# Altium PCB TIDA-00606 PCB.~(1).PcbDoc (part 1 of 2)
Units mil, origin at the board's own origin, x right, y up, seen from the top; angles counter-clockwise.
Board outline 3100 x 2950 mil, 4 copper layers (Top Layer, InternalPlane1, MidLayer1, Bottom Layer); 112 components, 59 nets, 260 pads, 440 vias.
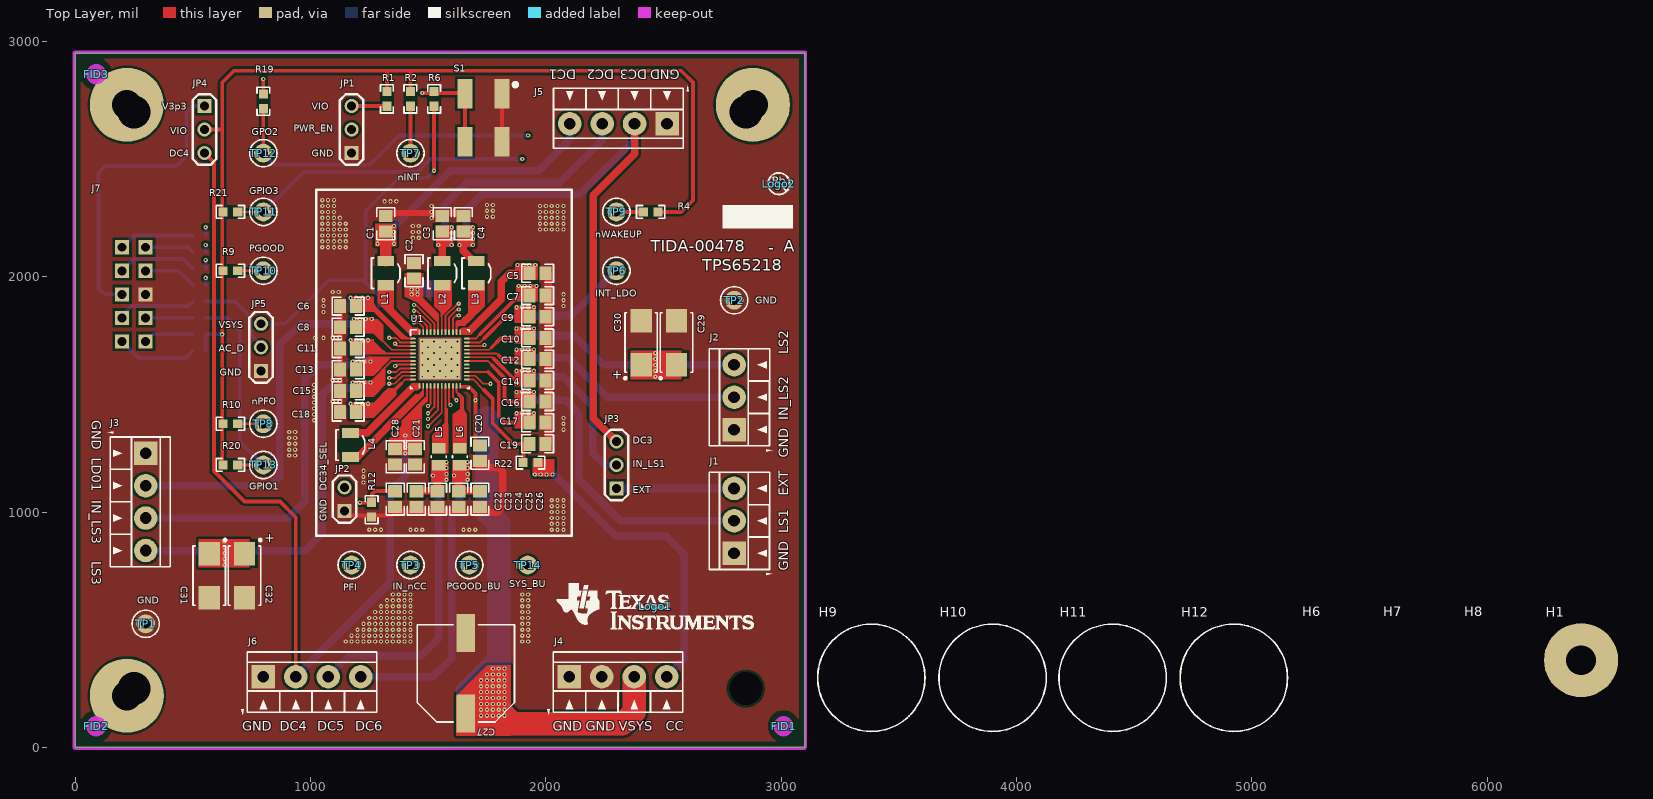
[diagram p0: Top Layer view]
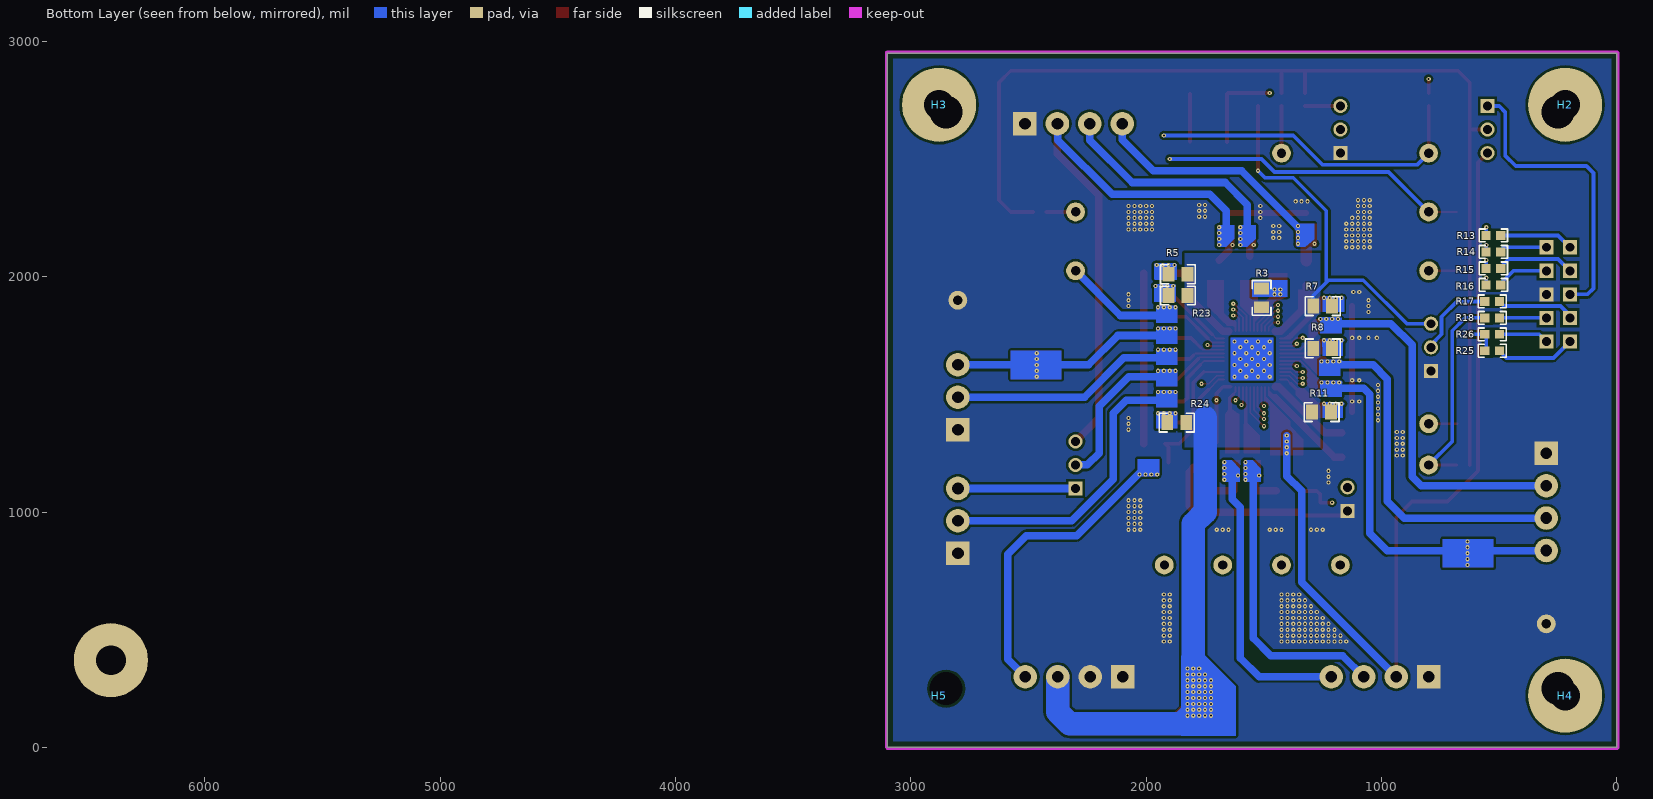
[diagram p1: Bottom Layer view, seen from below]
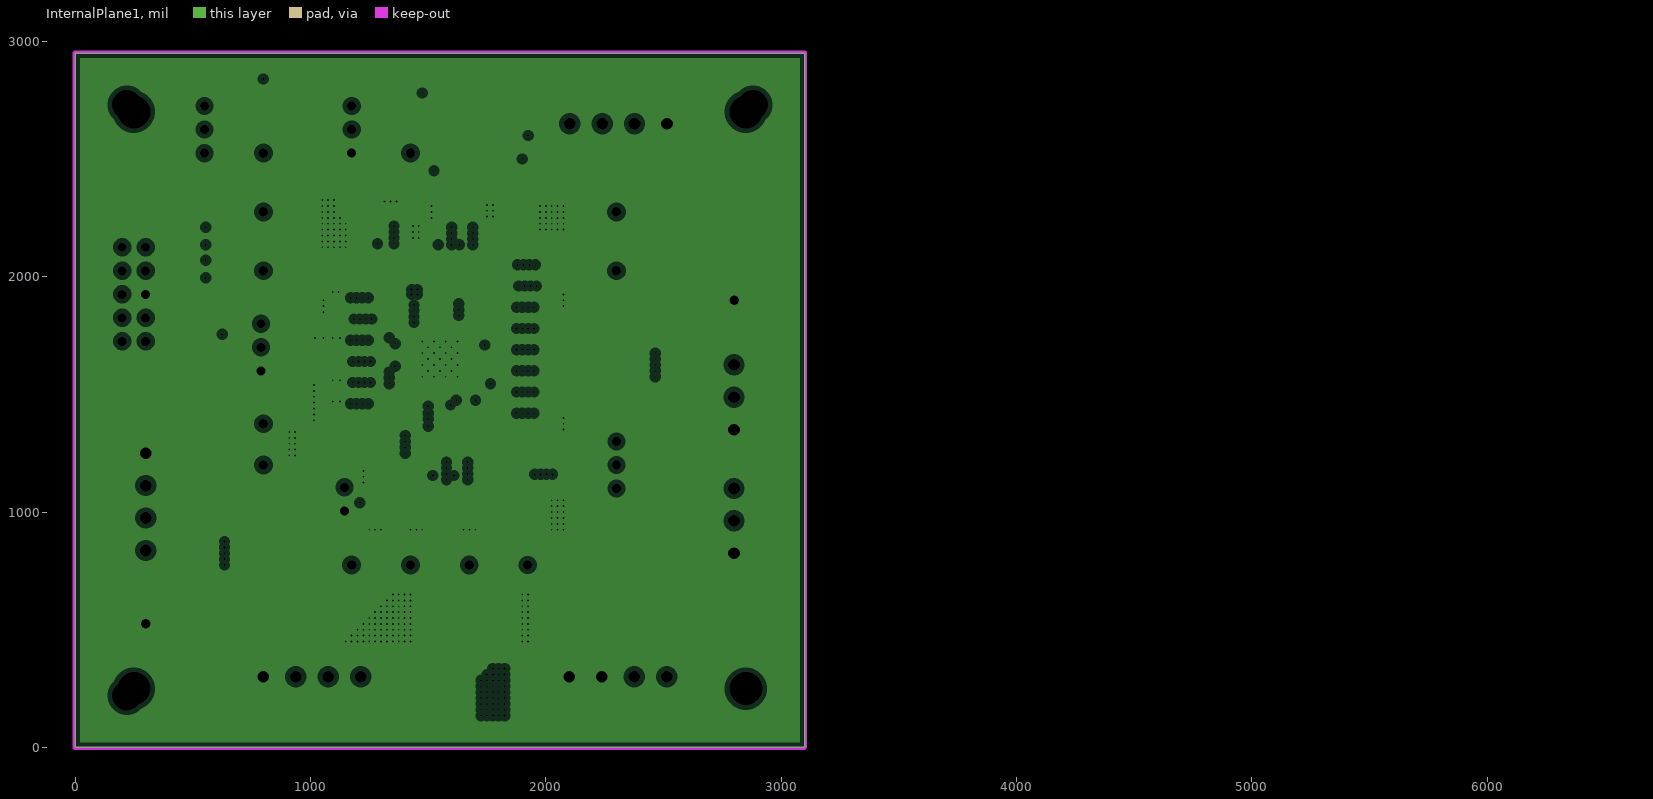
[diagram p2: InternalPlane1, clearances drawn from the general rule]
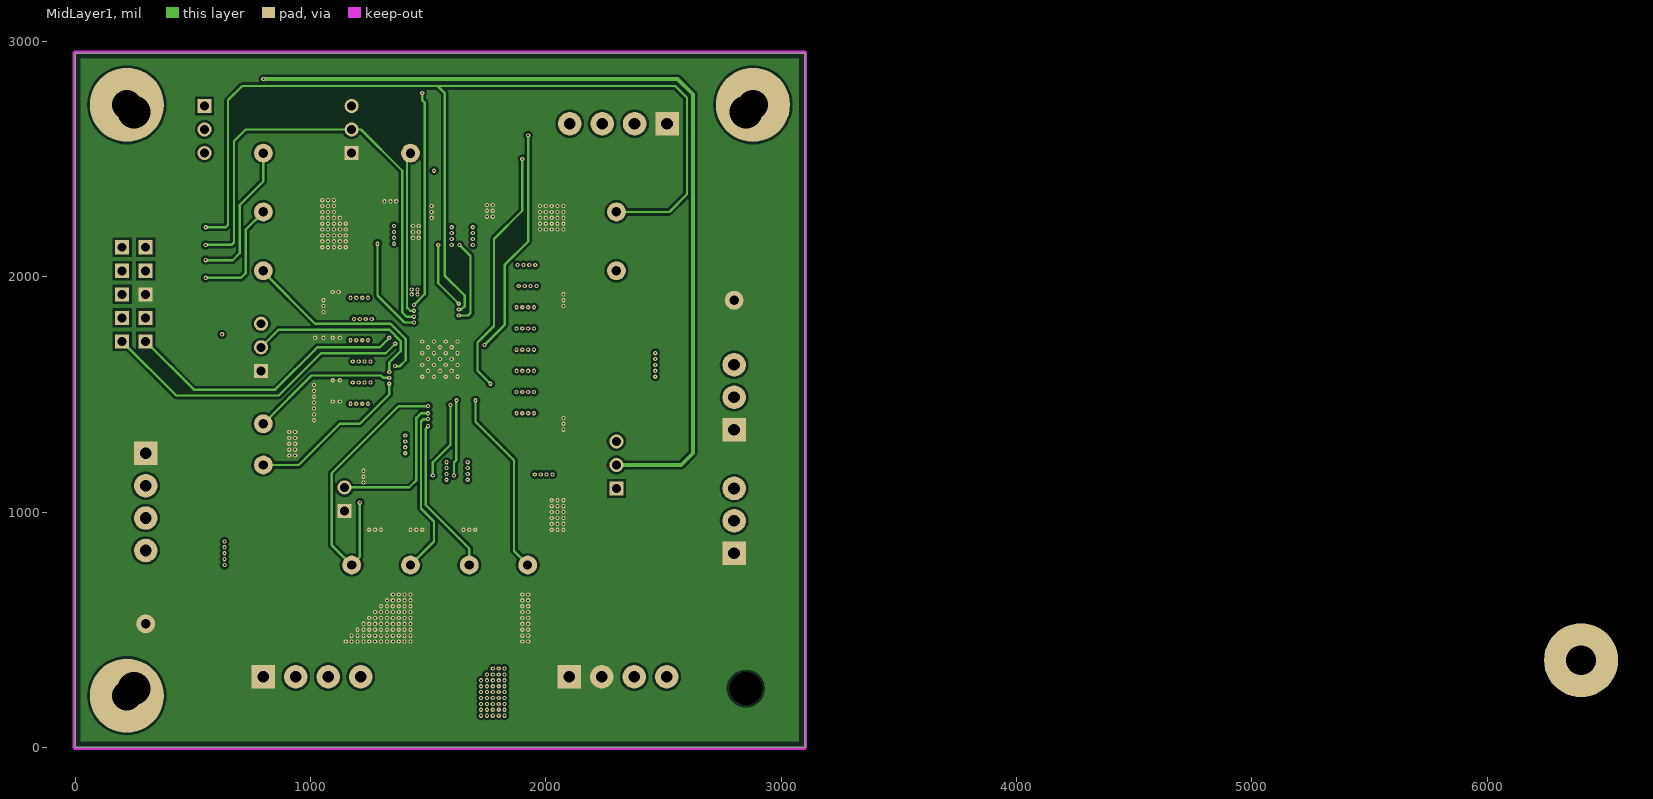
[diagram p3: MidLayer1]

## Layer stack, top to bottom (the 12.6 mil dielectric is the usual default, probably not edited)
Top Solder: solder mask 0.4, Solder Resist, Dk 3.5
Top Layer: signal copper 2.8
Dielectric1: core 12.6, FR-4, Dk 4.8
InternalPlane1: plane copper 2.1, net GND
Dielectric3: prepreg 12.6, FR-4, Dk 4.8
MidLayer1: signal copper 2.1
Dielectric2: core 12.6, FR-4, Dk 4.8
Bottom Layer: signal copper 2.8
Bottom Solder: solder mask 0.4, Solder Resist, Dk 3.5

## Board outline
0,0 3100,0 3100,2950 0,2950

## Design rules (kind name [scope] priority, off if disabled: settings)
AcuteAngle [All] p1: minimum=4.50000000000000E+0001 checktracksonly=FALSE
AssemblyTestPointUsage [All] p1 off: valid=2
AssemblyTestpoint [All] p1 off: testpointundercomponent=TRUE minsize=40 maxsize=100 preferedsize=60 minholesize=0 maxholesize=40 preferedholesize=32 testpointgrid=1 usegrid=TRUE gridtolerance=0.01 allowsidetop=TRUE allowsidebottom=TRUE
Clearance Clearance_BoardEdge_MountingHoles [OnCopper and InComponentClass('Mounting Holes') vs IsKeepOut] p1: gap=40
Clearance Clearance_BoardEdge_Poly [OnCopper and InPoly vs IsKeepOut] p2: gap=25
Clearance Clearance_BoardEdge [OnCopper and Not InComponentClass('Logo') and not InComponentClass('FiducialMark') and not InRegion(1000,500,4000,800) and Not IsKeepout vs IsKeepOut] p3: gap=50
Clearance Clearance_Poly [InPolygon] p4: gap=10
Clearance [All] p5: gap=5
ComponentClearance ComponentClearance_Shunt [InComponentClass('Header') vs InComponentClass('Shunt')] p1: gap=0 collisioncheckmode=3 verticalgap=0 showdistances=FALSE
ComponentClearance ComponentClearance_MountingHoles_FiducialMarks [InComponentClass('Mounting Holes') vs InComponentClass('FiducialMark')] p2: gap=50 collisioncheckmode=3 verticalgap=10 showdistances=FALSE
ComponentClearance ComponentClearance_Logo [InComponentClass('Logo')] p3: gap=50 collisioncheckmode=3 verticalgap=10 showdistances=FALSE
ComponentClearance ComponentClearance_ScrewToNut [(HasFootprint('NY PMS 440 0025 PH')) vs (HasFootprint('Keystone_1902C'))] p4: gap=5 collisioncheckmode=3 verticalgap=10 showdistances=FALSE
ComponentClearance ComponentClearance_MountingHoles [InComponentClass('Mounting Holes')] p5: gap=250 collisioncheckmode=3 verticalgap=100000 showdistances=FALSE
ComponentClearance ComponentClearance_SmallPassives [HasFootprint('0201*') or HasFootprint('0402*') or HasFootprint('0508') or HasFootprint('0603*') or HasFootprint('0612') or HasFootprint('0805*') or HasFootprint('0815*') or HasFootprint('0830*') or HasFootprint('1206*') or HasFootprint('1210*') or HasFootprint('1808*') or HasFootprint('1812*') or HasFootprint('1825*') or HasFootprint('2010*') or HasFootprint('2220*') or HasFootprint('2225*') or HasFootprint('2512*') or HasFootprint('2728*') or HasFootprint('3518*') vs HasFootprint('0201*') or HasFootprint('0402*') or HasFootprint('0508') or HasFootprint('0603*') or HasFootprint('0612') or HasFootprint('0805*') or HasFootprint('0815*') or HasFootprint('0830*') or HasFootprint('1206*') or HasFootprint('1210*') or HasFootprint('1808*') or HasFootprint('1812*') or HasFootprint('1825*') or HasFootprint('2010*') or HasFootprint('2220*') or HasFootprint('2225*') or HasFootprint('2512*') or HasFootprint('2728*') or HasFootprint('3518*')] p6: gap=20 collisioncheckmode=3 verticalgap=10 showdistances=FALSE
ComponentClearance ComponentClearance_THtoSMT [IsThruComponent vs IsSMTComponent] p7: gap=10 collisioncheckmode=3 verticalgap=30 showdistances=FALSE
ComponentClearance ComponentClearance_THtoTH [IsThruComponent vs IsThruComponent] p8: gap=10 collisioncheckmode=3 verticalgap=30 showdistances=FALSE
ComponentClearance [All] p9: gap=10 collisioncheckmode=3 verticalgap=10 showdistances=FALSE
DiffPairsRouting [All] p1: maxlimit=100 minlimit=10 mostfreqgap=10 toplayer_minwidth=15 toplayer_maxwidth=15 toplayer_prefwidth=15 midlayer2_minwidth=15 midlayer2_maxwidth=15 midlayer2_prefwidth=15 bottomlayer_minwidth=15 bottomlayer_maxwidth=15 bottomlayer_prefwidth=15 maxuncoupledlength=1000
FabricationTestPointUsage TestPointUsage [All] p1: valid=2 allowmultiple=FALSE
FabricationTestpoint Testpoint [All] p1: side=3 testpointundercomponent=TRUE minsize=40 maxsize=100 preferedsize=60 minholesize=0 maxholesize=40 preferedholesize=32 testpointgrid=1 allowsidetop=TRUE allowsidebottom=TRUE usegrid=TRUE gridtolerance=0.01
FanoutControl Fanout_LCC [IsLCC] p1: bgadir=Out bgaviamode=Centered fanoutstyle=Auto fanoutdirection=Alternating viagrid=1 // Fanout_LCC (Default Rule)
FanoutControl Fanout_BGA [IsBGA] p2: bgadir=Out bgaviamode=Centered fanoutstyle=Auto fanoutdirection=Alternating viagrid=1 // Fanout_BGA (Default Rule)
FanoutControl Fanout_Default [All] p4: bgadir=Out bgaviamode=Centered fanoutstyle=Auto fanoutdirection=Alternating viagrid=1 // Fanout_Default (Default Rule)
FanoutControl Fanout_Small [(CompPinCount < 5)] p5: bgadir=Out bgaviamode=Centered fanoutstyle=Auto fanoutdirection=OutThenIn viagrid=1 // Fanout_Small (Default Rule)
HoleSize [All] p1: absolutevalues=TRUE maxlimit=251 minlimit=8 maxpercent=80.000 minpercent=20.000
MinimumAnnularRing MinimumAnnularRing_ThermalPadVias [IsVia and InAnyComponent] p1: minimumring=5
MinimumAnnularRing [All] p2: minimumring=5
MinimumSolderMaskSliver MinimumSolderMaskSliver_Logo [InComponentClass('Logo') vs InComponentClass('Logo')] p1: minsoldermaskwidth=0.7
MinimumSolderMaskSliver [All] p2: minsoldermaskwidth=4
PlaneClearance [All] p1: clearance=20
PlaneConnect [All] p1: planeconnectstyle=Direct reliefexpansion=10 reliefentries=4 reliefconductorwidth=10 reliefairgap=10
PolygonConnect [All] p1: connectstyle=Direct reliefconductorwidth=10 reliefentries=4 polygonreliefangle="90 Angle" airgapwidth=10
RoutingVias ThermalPadVias [IsVia and InAnyComponent] p1: holewidth=7.87 width=19.68 viastyle="Through Hole" minholewidth=7.87 minwidth=18 maxholewidth=12.99 maxwidth=23.62
RoutingVias [All] p2: holewidth=16 width=34 viastyle="Through Hole" minholewidth=7.87 minwidth=18 maxholewidth=40 maxwidth=65
SMDToCorner [All] p1: distance=25000
SilkToSilkClearance SilkToSilkClearance_Pb-FreeLogo [(HasFootprint('Pb-Free_Overlay_Medium') OR HasFootprint('Pb-Free_Overlay_Small')) vs (HasFootprint('Pb-Free_Overlay_Medium') OR HasFootprint('Pb-Free_Overlay_Small'))] p1: silktosilkclearance=0
SilkToSilkClearance [All] p2: silktosilkclearance=5
SilkToSolderMaskClearance SilkscreenOverComponentPads [IsPad] p1: minsilkscreentomaskgap=4.5 clearancetoexposedcopper=TRUE
SolderMaskExpansion [All] p1: expansion=0
UnpouredPolygon [All] p1: allowunpoured=FALSE
Width [All] p1: maxlimit=100 minlimit=6 preferedwidth=10 checkconnectedcopper=TRUE
13 further rules are at their usual default settings.

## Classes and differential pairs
component class "Mounting Holes": H1 H2 H3 H4
component class TIDA0606: C1 C2 C3 C4 C5 C6 C7 C8 C9 C10 C11 C12 C13 C14 C15 C16 C17 C18 C19 C20 C21 C22 C23 C24 C25 C26 C27 C28 C29 C30 C31 C32 J1 J2 J3 J4 J5 J6 J7 JP1 JP2 JP3 JP4 JP5 L1 L2 L3 L4 L5 L6 R1 R2 R3 R4 R5 R6 R7 R8 R9 R10 R11 R12 R13 R14 R15 R16 R17 R18 R19 R20 R21 R22 R23 R24 R25 R26 S1 TP1 TP2 TP3 TP4 TP5 TP6 TP7 TP8 TP9 TP10 TP11 TP12 TP13 TP14 U1
component class Logo: Logo1
component class TID_Hardware: FID1 FID2 FID3 H1 H2 H3 H4 H5 H6 H7 H8 H9 H10 H11 H12 Logo1 Logo2 ZZ2 ZZ3 ZZ4
component class FiducialMark: FID1 FID2 FID3
component class AssemblyNote: ZZ3 ZZ4

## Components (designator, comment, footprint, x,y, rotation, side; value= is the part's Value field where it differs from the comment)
C1 "C2012X7R0J106K125AB" 0805 1320,2225 r90 top
C2 "C2012X7R1A475K125AC" 0805 1440,2025 r90 top
C3 "C2012X7R0J106K125AB" 0805 1560,2225 r90 top
C4 "C2012X7R0J106K125AB" 0805 1650,2225 r90 top
C5 "C2012X7R1A475K125AC" 0805 1965,2014.68 r0 top
C6 "C2012X7R1A475K125AC" 0805 1160,1875 r0 top
C7 "C2012X7R1A475K125AC" 0805 1965,1919.68 r0 top
C8 "C2012X7R0J106K125AB" 0805 1160,1785 r0 top
C9 "C0805C104K8RACTU" 0805 1965,1829.68 r0 top
C10 "C2012X7R1A106K125AC" 0805 1965,1739.68 r0 top
C11 "C2012X7R1A475K125AC" 0805 1160,1695 r0 top
C12 "C2012X7R1A475K125AC" 0805 1965,1649.68 r0 top
C13 "C2012X7R1C475K125AE" 0805 1160,1605 r0 top
C14 "C2012X7R1A475K125AC" 0805 1965,1559.68 r0 top
C15 "CL21B106KOQNNNE" 0805 1160,1515 r0 top
C16 "C2012X7R1A106K125AC" 0805 1965,1469.68 r0 top
C17 "C2012X7R1A475K125AC" 0805 1965,1379.68 r0 top
C18 "C2012X7R1A475K125AC" 0805 1160,1425 r0 top
C19 "C2012X7R1A475K125AC" 0805 1965,1289.68 r0 top
C20 "CL21B105KPFNNNE" 0805 1720,1250 r90 top
C21 "C0805C104K8RACTU" 0805 1445,1235 r90 top
C22 "C0805C104K8RACTU" 0805 1360,1055 r90 top
C23 "C2012X7R1A106K125AC" 0805 1450,1055 r90 top
C24 "C2012X7R1A106K125AC" 0805 1540,1055 r90 top
C25 "C2012X7R1A106K125AC" 0805 1630,1055 r90 top
C26 "C2012X7R1A106K125AC" 0805 1720,1055 r90 top
C27 "EEE-1EA471UAP" SM_RADIAL_G 1660,315 r90 top
C28 "C2012X5R1A476M125AC" 0805 1360,1235 r90 top
C29 "T495C686M016ZTE250" 6032-28 2555,1720 r90 top
C30 "T495C686M016ZTE250" 6032-28 2405,1720 r90 top
C31 "T495C686M016ZTE250" 6032-28 570,730 r270 top
C32 "T495C686M016ZTE250" 6032-28 720,730 r270 top
FID1 "Fiducial" Fiducial10-20 3010,90 r0 top
FID2 "Fiducial" Fiducial10-20 90,90 r0 top
FID3 "Fiducial" Fiducial10-20 90,2860 r0 top
H1 "NY PMS 440 0025 PH" "NY PMS 440 0025 PH" 6398,371 r0 top
H2 "NY PMS 440 0025 PH" "NY PMS 440 0025 PH" 220,2730 r180 bottom
H3 "NY PMS 440 0025 PH" "NY PMS 440 0025 PH" 2880,2730 r180 bottom
H4 "NY PMS 440 0025 PH" "NY PMS 440 0025 PH" 220,220 r180 bottom
H5 "1902C" Keystone_1902C#1 2880,220 r180 bottom
H6 "1902C" Keystone_1902C#2 5353,401 r0 top
H7 "1902C" Keystone_1902C#2 5698,401 r0 top
H8 "1902C" Keystone_1902C#2 6043,401 r0 top
H9 "SJ-5303 (CLEAR)" Bumpon_SJ5003Transparent 3383,296 r0 top
H10 "SJ-5303 (CLEAR)" Bumpon_SJ5003Transparent 3898,296 r0 top
H11 "SJ-5303 (CLEAR)" Bumpon_SJ5003Transparent 4408,296 r0 top
H12 "SJ-5303 (CLEAR)" Bumpon_SJ5003Transparent 4923,296 r0 top
J1 "ED555/3DS" TERM_BLK_ED555-3DS 2800,825 r90 top
J2 "ED555/3DS" TERM_BLK_ED555-3DS 2800,1350 r90 top
J3 "ED555/4DS" TERM_BLK_ED555-4DS 300,1250 r270 top
J4 "ED555/4DS" TERM_BLK_ED555-4DS 2100,300 r0 top
J5 "ED555/4DS" TERM_BLK_ED555-4DS 2515,2650 r180 top
J6 "ED555/4DS" TERM_BLK_ED555-4DS 800,300 r0 top
J7 "CONN_2510-6002UB" CONN_2510-6002UB 200,2125 r270 top
JP1 "PWR_EN" HDR100_1X3 1175,2525 r90 top
JP2 "DC34_SEL" HDR100_1X2 1145,1005 r90 top
JP3 "IN_LS1" HDR100_1X3 2300,1100 r90 top
JP4 "VIO" HDR100_1X3 550,2725 r270 top
JP5 "AC_DET" HDR100_1X3 790,1600 r90 top
L1 "SPM3012T-1R5M" SPM3012 1320,2015 r90 top
L2 "SPM3012T-1R5M" SPM3012 1560,2015 r90 top
L3 "SPM3012T-1R5M" SPM3012 1705,2015 r90 top
L4 "SPM3012T-1R5M" SPM3012 1170,1285 r90 top
L5 "MLZ2012N100LT000" 0805_145 1545,1235 r90 top
L6 "MLZ2012N100LT000" 0805_145 1635,1235 r90 top
Logo1 "Texas Instruments" TI_Stacked_Overlay_Small 2465,600 r0 top
Logo2 "Pb-Free Symbol" Pb-Free_Overlay_Small 2990,2395 r0 top
R1 "CRCW0603100KFKEA" 0603 1325,2755 r90 top
R2 "CRCW0603100KFKEA" 0603 1425,2755 r90 top
R3 "CRCW08050000Z0EAHP" 0805_HV 1510,1910 r270 bottom
R4 "CRCW0603100KFKEA" 0603 2445,2275 r0 top
R5 "CRCW08050000Z0EAHP" 0805_HV 1865,2010 r180 bottom
R6 "CRCW0603100KFKEA" 0603 1525,2755 r270 top
R7 "CRCW08050000Z0EAHP" 0805_HV 1250,1875 r180 bottom
R8 "CRCW08050000Z0EAHP" 0805_HV 1250,1695 r180 bottom
R9 "CRCW0603100KFKEA" 0603 660,2025 r0 top
R10 "CRCW0603100KFKEA" 0603 660,1375 r0 top
R11 "CRCW08050000Z0EAHP" 0805_HV 1255,1425 r180 bottom
R12 "CRCW0603100KFKEA" 0603 1260,1010 r90 top
R13 "CRCW06031K00FKEA" 0603 525,2175 r0 bottom
R14 "CRCW06031K00FKEA" 0603 525,2105 r0 bottom
R15 "CRCW06031K00FKEA" 0603 525,2035 r0 bottom
R16 "CRCW06031K00FKEA" 0603 525,1965 r0 bottom
R17 "CRCW06031K00FKEA" 0603 530,1895 r0 bottom
R18 "CRCW06031K00FKEA" 0603 530,1825 r0 bottom
R19 "CRCW0603100KFKEA" 0603 800,2745 r90 top
R20 "CRCW0603100KFKEA" 0603 660,1200 r0 top
R21 "CRCW0603100KFKEA" 0603 660,2275 r180 top
R22 "CRCW060310R0JNEAHP" 0603 1935,1210 r0 top
R23 "CRCW08050000Z0EAHP" 0805_HV 1865,1920 r180 bottom
R24 "CRCW08050000Z0EAHP" 0805_HV 1870,1380 r180 bottom
R25 "CRCW06034K75FKEA" 0603 530,1685 r0 bottom
R26 "CRCW06034K75FKEA" 0603 530,1755 r0 bottom
S1 "KT11P2JM34LFS" SW_KT11P2JM 1735,2675 r270 top
TP1 "GND" Keystone5001 300,525 r0 top
TP2 "GND" Keystone5001 2800,1900 r90 top
TP3 "IN_nCC" Keystone5002 1425,775 r90 top
TP4 "PFI" Keystone5002 1175,775 r0 top
TP5 "PGOOD_BU" Keystone5002 1675,775 r90 top
TP6 "INT_LDO" Keystone5002 2300,2025 r90 top
TP7 "nINT" Keystone5002 1425,2525 r90 top
TP8 "nPFO" Keystone5002 800,1375 r90 top
TP9 "nWAKEUP" Keystone5002 2300,2275 r90 top
TP10 "PGOOD" Keystone5002 800,2025 r90 top
TP11 "GPIO3" Keystone5002 800,2275 r90 top
TP12 "GPO2" Keystone5002 800,2525 r90 top
TP13 "GPIO1" Keystone5002 800,1200 r90 top
TP14 "SYS_BU" TESTPOINT 1923,775 r90 top
U1 "TPS65218RSL" RSL0048B_NV 1550,1650 r0 top locked
ZZ2 "These assemblies are ESD sensitive, ESD precautions shall be observed." AssemblyNote 185,3829.11 r0 top
ZZ3 "These assemblies must be clean and free from flux and all contaminants. Use of no clean flux is not acceptable." AssemblyNote 185,3740.56 r0 top
ZZ4 "These assemblies must comply with workmanship standards IPC-A-610 Class 2, unless otherwise specified." AssemblyNote 185,3652 r0 top

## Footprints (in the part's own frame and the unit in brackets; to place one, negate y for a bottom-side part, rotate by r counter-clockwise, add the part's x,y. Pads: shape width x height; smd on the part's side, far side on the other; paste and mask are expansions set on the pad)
0603 [mm] "0603 from SM-752 data"
  rect 1x0.95 smd: 1(-0.8,0) 2(0.8,0)
  silkscreen extent -1.52,-0.69 1.52,0.69, body extent -0.87,-0.47 0.87,0.47, height 0.85
0805 [mm] "0805 from SM-752 data"
  rect 1.3x1.5 smd: 1(-0.85,0) 2(0.85,0)
  silkscreen extent -1.72,-0.97 1.72,0.97, body extent -1.1,-0.72 1.1,0.72, height 1.1
0805_145 [mm] "0805 / 1.45mm height"
  rect 1.15x1.45 smd: 1(-0.9,0) 2(0.9,0)
  silkscreen extent -0.1,-0.8 0.1,0.8, body extent -1.1,-0.72 1.1,0.72, height 1.4
0805_HV [mil] "0805 with 30mil clearance between pads"
  rect 50x63 smd: 1(-40,0) 2(40,0)
  silkscreen extent -74,-40 74,40, body extent -43,-29 43,29, height 43
6032-28 [mm] "Medium Density IPC based on Vishay Sprague 293D datasheet."
  rect 2.55x2.3 smd: 1(-2.375,0) 2(2.375,0)
  silkscreen extent -3.96,-1.75 3.2,1.82, body extent -3.15,-1.75 3.15,1.75, height 2.8
AssemblyNote [mil] "Assembly Note"
Bumpon_SJ5003Transparent [mil] "3M Hemispherical Bumpon transparent"
  round 1 on Mech3: 0(0,0)
  silkscreen extent -228,-228 228,228, body extent -217,-218 219,218, height 197
CONN_2510-6002UB [mil]
  rect 60x60 hole 38: 1(0,0) 2(0,100) 3(100,0) 4(100,100) 5(200,0) 6(200,100) 7(300,0) 8(300,100) 9(400,0) 10(400,100)
Fiducial10-20 [mm]
  round 1 smd mask+0.5: 1(0,0)
  Top Layer keep-out circle w1.178: c0,0 r0.5
HDR100_1X2 [mil]
  rect 60x60 hole 38: 1(0,0)
  round 60 hole 38: 2(100,0)
  silkscreen extent -50,-50 150,50
HDR100_1X3 [mil]
  rect 60x60 hole 38: 1(0,0)
  round 60 hole 38: 2(100,0) 3(200,0)
  silkscreen extent -50,-50 250,50
Keystone5001 [mil] "For Keystone 500x miniature loop terminals"
  round 80 hole 40: 1(0,0)
  silkscreen extent -58,-58 58,58, body extent -49,-49 49,49, height 182
Keystone5002 [mil] "For Keystone 500x miniature loop terminals"
  round 80 hole 40: 1(0,0)
  silkscreen extent -58,-58 58,58, body extent -49,-49 49,49, height 182
Keystone_1902C#1 [mil] "Hex Standoff, 4-40 threaded, nylon"
  round 1 on Mech4: 0(0,0)
  body extent -145,-126 146,126, height 501
Keystone_1902C#2 [mil] "Hex Standoff, 4-40 threaded, nylon"
  round 1 on Mech3: 0(0,0)
  body extent -145,-126 146,126, height 501
"NY PMS 440 0025 PH" [mm] "4-40 nylon screw and mounting hole"
  round 8 hole 3.2: 1(0,0)
  body extent -3.3,-3.3 3.3,3.3, height 2.69
Pb-Free_Overlay_Small [mil]
  silkscreen extent -46,-46 46,46
RSL0048B_NV [mm]
  oval 0.6x0.2 smd: 1(-2.9,2.2) 2(-2.9,1.8) 3(-2.9,1.4) 4(-2.9,1) 5(-2.9,0.6) 6(-2.9,0.2) 7(-2.9,-0.2) 8(-2.9,-0.6) 9(-2.9,-1) 10(-2.9,-1.4) 11(-2.9,-1.8) 12(-2.9,-2.2) 25(2.9,-2.2) 26(2.9,-1.8) 27(2.9,-1.4) 28(2.9,-1) 29(2.9,-0.6) 30(2.9,-0.2) 31(2.9,0.2) 32(2.9,0.6) 33(2.9,1) 34(2.9,1.4) 35(2.9,1.8) 36(2.9,2.2)
  oval 0.2x0.6 smd: 13(-2.2,-2.9) 14(-1.8,-2.9) 15(-1.4,-2.9) 16(-1,-2.9) 17(-0.6,-2.9) 18(-0.2,-2.9) 19(0.2,-2.9) 20(0.6,-2.9) 21(1,-2.9) 22(1.4,-2.9) 23(1.8,-2.9) 24(2.2,-2.9) 37(2.2,2.9) 38(1.8,2.9) 39(1.4,2.9) 40(1,2.9) 41(0.6,2.9) 42(0.2,2.9) 43(-0.2,2.9) 44(-0.6,2.9) 45(-1,2.9) 46(-1.4,2.9) 47(-1.8,2.9) 48(-2.2,2.9)
  rect 4.4x4.4 smd paste-2.2: 49(0,0)
  silkscreen extent -3.17,-3.17 3.17,3.17, body extent -3.07,-3.07 3.07,3.07, height 1.01
SM_RADIAL_G [mm] "10 x 10.2mm:  Panasonic G"
  rect 4.1x2 smd: 1(-4.35,0) 2(4.35,0)
  silkscreen extent -5.25,-5.25 5.25,5.25, body extent -5.26,-5.26 5.26,5.26, height 10.5
SPM3012 [mm] "SMD, 2-Leads, Body 3.2x3mm"
  rect 1.1x1.8 smd: 1(-1.3,0) 2(1.3,0)
  silkscreen extent -1.65,-1.55 1.65,1.55, body extent -1.65,-1.55 1.65,1.55, height 1.2
SW_KT11P2JM [mm] "C&K"
  rect 3.175x1.59 smd: 1(-2.602,2) 2(-2.602,-2) 3(2.603,-2) 4(2.603,2)
  silkscreen extent -3.77,3.25 -3.38,3.65, body extent -3,-3 3,3, height 5.36
TERM_BLK_ED555-3DS [mm]
  rect 2.54x2.54 hole 1.27: 1(0,0)
  round 2.54 hole 1.27: 2(3.5,0) 3(7,0)
  silkscreen extent -2.36,-4.09 8.75,2.67, body extent -1.75,-3.83 8.75,2.67, height 8.2
TERM_BLK_ED555-4DS [mm]
  rect 2.54x2.54 hole 1.27: 1(0,0)
  round 2.54 hole 1.27: 2(3.5,0) 3(7,0) 4(10.5,0)
  silkscreen extent -2.36,-4.09 12.25,2.67, body extent -1.75,-3.8 12.25,2.7, height 8.2
TESTPOINT [mil]
  round 80 hole 37.99: 1(0,0)
TI_Stacked_Overlay_Small [mil]
  silkscreen extent -418,-98 418,98

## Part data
C1 C3 C4 C8: library part Capacitor, "CAP, CERM, 10F, 6.3V, X7R, 10%, 0805"
C2 C5 C6 C7 C11 C12 C14 C17 C18 C19: library part Capacitor, "CAP, CERM, 4.7uF, 10V, X7R, 10%, 0805"
C9 C21 C22: library part Capacitor, "CAP, CERM, 100nF, 10V, X7R, 10%, 0805"
C10 C16 C23 C24 C25 C26: library part Capacitor, "CAP, CERM, 10uF, 10V, X7R, 10%, 0805"
C13: library part Capacitor, "CAP, CERM, 4.7uF, 16V, X7R, 10%, 0805"
C15: library part Capacitor, "CAP, CERM, 10uF, 16V, X7R, 10%, 0805"
C20: library part Capacitor, "CAP, CERM, 1uF, 10V, X7R, 10%, 0805"
C27: library part Capacitor_Polarized, "CAP, ALUM, 470uF, 25V, +/-20%, SMD"
C28: library part Capacitor, "CAP, CERM, 47uF, 10V, X5R, 20%, 0805"
C29 C30 C31 C32: library part Capacitor_Polarized, "CAP, TANT, 68uF, 16V, +/-20%, 250mOhm ESR, SMT"
FID1 FID2 FID3: "Fiducial mark.  There is nothing to buy or mount."
H1 H2 H3 H4: "Machine Screw, Round, #4-40 x 1/4, Nylon, Philips panhead"
H5 H6 H7 H8: "Standoff, Hex, 0.5\"L #4-40 Nylon"
H9 H10 H11 H12: "Bumpon, Hemisphere, 0.44 X 0.20, Clear"
J1 J2: "Terminal Block, 6A, 3.5mm Pitch, 3-Pos, TH"
J3 J4 J5 J6: "Terminal Block, 6A, 3.5mm Pitch, 4-Pos, TH"
J7: "Connector, Male Straight 2x5 pin, 100mil spacing, 4 Wall"
JP1 JP3 JP4 JP5: library part JUMPER_3X100MIL, "Header, Male 3-pin, 100mil spacing,"
JP2: library part JUMPER_2X100MIL, "Header, Male 2-pin, 100mil spacing,"
L1 L2 L3 L4: "Inductor, Shielded, Ferrite, 1.5uH, 2.8A, 0.09 ohm, SMD"
L5 L6: "Inductor, Multilayer, Ferrite, 10uH, 0.5A, 0.3 ohm, SMD"
Logo1: library part TI_Logo, "Texas Instrument Corporate Signature"
Logo2: library part Pb-Free
R1 R2 R4 R6 R9 R10 R12 R19 R20 R21: "RES, 100 k, 1%, 0.1 W, 0603"
R3 R5 R7 R8 R11 R23 R24: "RES, 0 ohm, 5%, 0.333W, 0805"
R13 R14 R15 R16 R17 R18: "RES, 1.00 k, 1%, 0.1 W, 0603"
R22: "RES, 10, 5%, 0.25 W, 0603"
R25 R26: "RES, 4.75 k, 1%, 0.1 W, 0603"
S1: "Switch, Tactile, SPST-NO, 1VA, 32V, SMT"
TP1 TP2: library part 5001, "Test Point, Miniature, Black, TH"
TP3 TP4 TP5 TP6 TP7 TP8 TP9 TP10 TP11 TP12 TP13: library part 5002, "Test Point, Miniature, White, TH"
TP14: library part TESTPOINT, "TEST POINT.  No entry in BOM."
U1: "Power Management for AM335x / AM437x ARM® Cortex™-A8 / A9 SOCs, RSL0048B"
ZZ2 ZZ3 ZZ4: library part AssemblyNote

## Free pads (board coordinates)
  round 60 hole 140: 0(250,250) 0(250,2700) 0(2850,250) 0(2850,2700)

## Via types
v1: diameter 18, hole 8, Top Layer to Bottom Layer, tented both sides, 440 vias

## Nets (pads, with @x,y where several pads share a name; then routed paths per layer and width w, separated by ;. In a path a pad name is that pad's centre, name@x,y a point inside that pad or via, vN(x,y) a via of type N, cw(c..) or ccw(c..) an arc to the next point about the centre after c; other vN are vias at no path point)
1V1_VCC: C1.1 J5.4 L1.2 U1.47 | length 1756.4
  Top Layer w8: v1(1440,1805) 1459.43,1805 1479.13,1785.3 U1.47@1479.13,1768.11
  Top Layer w16: v1(1355,2140) v1(1355,2165) v1(1355,2190) v1(1355,2215)
  Top Layer w48: L1.2@1320,2066.18 C1.1@1320,2180
  MidLayer1 w10: v1(1285,2140) 1285,1920 1400,1805 v1(1440,1805)
  Bottom Layer w16: v1@1355,2135 v1(1355,2140) v1(1355,2165) v1(1355,2190) 1355,2210 v1(1355,2215)
  Bottom Layer w32: 1332.5,2187.5 1355,2210 1595,2450 1970,2450 2101,2581 J5.4@2101,2650
1V1_VCC_GXB: C3.1 J5.3 L2.2 U1.41 | length 1651.2
  Top Layer w8: U1.41@1573.62,1768.11 1573.62,1833.05 1625.57,1885 v1(1630,1885)
  Top Layer w16: v1(1600,2135) v1(1600,2160) v1(1600,2185) v1(1600,2210)
  Top Layer w32: L2.2@1560,2086.18 C3.1@1560,2180
  MidLayer1 w10: v1(1543,2135) 1543,1972 v1(1630,1885)
  Bottom Layer w16: v1(1600,2135) v1(1600,2160) v1(1600,2185) v1(1600,2210)
  Bottom Layer w32: 1570,2180 1570,2305 1665,2400 2060,2400 2239,2579 J5.3@2239,2650
1V8: C8.2 J3.2 U1.4 | length 1924.5
  Top Layer w8: 1250,1785 1345.63,1689.37 U1.4@1431.89,1689.37
  Top Layer w16: v1(1185,1820) v1(1210,1820) v1(1235,1820) v1(1260,1820) ; C8.2@1215,1785 1250,1785
  Bottom Layer w16: v1@1180,1820 v1(1185,1820) v1(1210,1820) v1(1235,1820) v1(1260,1820)
  Bottom Layer w32: J3.2@300,1112 832,1112 870,1150 870,1710 960,1800 1200,1800
2V5: C4.1 J5.2 JP3.3 L3.2 U1.39 | length 3206.7
  Top Layer w8: U1.39@1605.12,1768.11 1605.12,1822.12 1618,1835 v1(1630,1835)
  Top Layer w16: v1(1690,2135) v1(1690,2160) v1(1690,2185) v1(1690,2210)
  Top Layer w32: C4.1@1650,2180 1650,2110 L3.2@1689.41,2070.59 ; JP3.3@2300,1300 2201,1399 2201,2346 2377,2522 J5.2@2377,2650
  MidLayer1 w10: v1(1630,1835) 1670,1835 1680,1845 1680,2088 v1(1633,2135)
  Bottom Layer w16: v1(1690,2135) v1(1690,2160) v1(1690,2185) v1(1690,2210)
  Bottom Layer w32: 1660,2170 1660,2280 1730,2350 2145,2350 2375,2580 J5.2@2375,2650
3V3: C21.2 C28.2 J6.2 JP4.3 U1.15 | length 4174
  Top Layer w8: 1391,1340 1391,1386.66 1494.88,1490.54 ; 1415,1342 1415,1392 1480,1457 1480,1458.28 1491.72,1470 1493,1470 1494.88,1471.88 1494.88,1490.54 ; U1.15@1494.88,1531.89 1494.88,1490.54
  Top Layer w16: JP4.3@550,2525 590,2485 590,1175 720,1045 871,1045 938,978 J6.2@938,300 ; C21.2@1448,1280 C21.2@1460,1292
  Top Layer w32: v1(1403,1300) v1(1403,1325) 1403,1348
  Bottom Layer w32: J6.2@938,300 1340,702 1340,1090 1403,1153 v1(1403,1250) v1(1403,1275) v1(1403,1300) v1(1403,1325)
AC_DET: JP5.2 R17.2 U1.9 | length 1264.8
  Top Layer w8: v1(1335,1595) 1365,1595 1380.63,1610.63 U1.9@1431.89,1610.63
  MidLayer1 w10: JP5.2@790,1700 865,1775 1335,1775 1383,1727 1383,1683 1335,1635 v1(1335,1595)
  Bottom Layer w16: R17.2@555,1895 R17.2@561.5,1895 680,1895 745,1830 745,1755 790,1710 JP5.2@790,1700
CC: J4.4 R22.2 | length 1451.3
  Top Layer w16: v1(1953,1160) v1(1978,1160) v1(2003,1160) v1(2028,1160)
  Bottom Layer w16: v1(1953,1160) v1(1978,1160) v1(2003,1160) v1(2028,1160)
  Bottom Layer w32: 1991,1186 2009,1186 2295,900 2510,900 2589,821 2589,375 J4.4@2514,300
DC34_SEL: JP2.2 U1.17 | length 763.5
  Top Layer w8: v1(1500,1420) 1526.38,1446.38 U1.17@1526.38,1531.89
  MidLayer1 w10: JP2.2@1145,1105 1420,1105 1450,1135 1450,1400 1470,1420 v1(1500,1420)
GND: C1.2 C2.2 C3.2 C4.2 C5.2 C6.1 C7.2 C8.1 C9.2 C10.2 C11.1 C12.2 C13.1 C14.2 C15.1 C16.2 C17.2 C18.1 C19.2 C20.1 C21.1 C22.1 C23.1 C24.1 C25.1 C26.1 C27.2 C28.1 C29.2 C30.2 C31.2 C32.2 J1.1 J2.1 J3.1 J4.1 J4.2 J5.1 J6.1 J7.6 JP1.1 JP2.1 JP5.1 R12.1 S1.1 S1.4 TP1.1 TP2.1 U1.49 | length 2674.8
  Top Layer w16: JP2.1@1145,1005 1165,985 1343,985 C22.1@1358,1000 ; S1.1@1813.85,2777.4 1813.85,2572.8 S1.4@1813.9,2572.75
  Top Layer w25: C18.1@1125,1425 v1(1125,1470) v1(1125,1560) v1(1125,1740) C6.1@1125,1875 ; C1.2@1320,2270 C4.2@1650,2270
  Top Layer w32: C22.1@1358,1000 1720,1000 1793,1000 1818,1025 1818,1170 1798,1190 1718,1190 ; C19.2@2010,1290 2010,1649.68 2010,1919.68 C5.2@2010,2015
  Bottom Layer w16: J4.2@2238,300 J4.2@2240,300
  Bottom Layer w32: J4.2@2238,300 J4.2@2238,312
  other v1: 1150,450 1175,450 1200,450 1225,450 1250,450 1275,450 1300,450 1325,450 1350,450 1375,450 1400,450 1425,450 1900,450 1925,450 1175,475 1200,475 1225,475 1250,475 1275,475 1300,475 1325,475 1350,475 1375,475 1400,475 1425,475 1900,475 1925,475 1200,500 1225,500 1250,500 1275,500 1300,500 1325,500 1350,500 1375,500 1400,500 1425,500 1900,500 1925,500 1225,525 1250,525 1275,525 1300,525 1325,525 1350,525 1375,525 1400,525 1425,525 1900,525 1925,525 1250,550 1275,550 1300,550 1325,550 1350,550 1375,550 1400,550 1425,550 1900,550 1925,550 1275,575 1300,575 1325,575 1350,575 1375,575 1400,575 1425,575 1900,575 1925,575 1300,600 1325,600 1350,600 1375,600 1400,600 1425,600 1900,600 1925,600 1325,625 1350,625 1375,625 1400,625 1425,625 1900,625 1925,625 1350,650 1375,650 1400,650 1425,650 1900,650 1925,650 1250,925 1275,925 1300,925 1425,925 1450,925 1475,925 1650,925 1675,925 1700,925 2025,925 2050,925 2075,925 2025,950 2050,950 2075,950 2025,975 2050,975 2075,975 2025,1000 2050,1000 2075,1000 2025,1025 2050,1025 2075,1025 2025,1050 2050,1050 2075,1050 1225,1125 1225,1150 1225,1175 910,1240 935,1240 910,1265 935,1265 910,1290 935,1290 910,1315 935,1315 910,1340 935,1340 2075,1350 2075,1375 1015,1390 2075,1400 1015,1415 1015,1440 1015,1465 1095,1470 1015,1490 1015,1515 1015,1540 1095,1560 1475,1575 1525,1575 1575,1575 1625,1575 1500,1600 1550,1600 1600,1600 1475,1625 1525,1625 1575,1625 1625,1625 1500,1650 1550,1650 1600,1650 1475,1675 1525,1675 1575,1675 1625,1675 1500,1700 1550,1700 1600,1700 1475,1725 1525,1725 1575,1725 1625,1725 1020,1740 1055,1740 1095,1740 1055,1850 1055,1875 2075,1875 1055,1900 2075,1900 2075,1925 1095,1935 1120,1935 1050,2125 1075,2125 1100,2125 1125,2125 1150,2125 1050,2150 1075,2150 1100,2150 1125,2150 1150,2150 1435,2165 1460,2165 1050,2175 1075,2175 1100,2175 1125,2175 1150,2175 1435,2190 1460,2190 1050,2200 1075,2200 1100,2200 1125,2200 1150,2200 1975,2200 2000,2200 2025,2200 2050,2200 2075,2200 1435,2215 1460,2215 1050,2225 1075,2225 1100,2225 1125,2225 1150,2225 1975,2225 2000,2225 2025,2225 2050,2225 2075,2225 1050,2250 1075,2250 1100,2250 1125,2250 1515,2250 1975,2250 2000,2250 2025,2250 2050,2250 2075,2250 1750,2255 1775,2255 1050,2275 1075,2275 1100,2275 1515,2275 1975,2275 2000,2275 2025,2275 2050,2275 2075,2275 1750,2280 1775,2280 1050,2300 1075,2300 1100,2300 1515,2300 1975,2300 2000,2300 2025,2300 2050,2300 2075,2300 1750,2305 1775,2305 1315,2320 1340,2320 1365,2320 1050,2325 1075,2325 1100,2325
GPIO1: R18.2 R20.2 TP13.1 U1.11 | length 1714.5
  Top Layer w8: v1(1335,1545) 1357.43,1545 1391.56,1579.13 U1.11@1431.89,1579.13
  Top Layer w12: R20.2@680,1200 R20.2@691.5,1200 TP13.1@800,1200
  MidLayer1 w10: TP13.1@800,1200 950,1200 1125,1375 1210,1375 1335,1500 v1(1335,1545)
  Bottom Layer w16: R18.2@555,1825 R18.2@561.5,1825 645,1825 700,1770 700,1300 TP13.1@800,1200
GPIO3: R16.2 R21.1 TP11.1 U1.26 | length 2980.1
  Top Layer w8: U1.26@1668.11,1579.13 1700.87,1579.13 1735,1545 v1(1765,1545)
  Top Layer w10: R21.1@680,2275 R21.1@691.5,2275 TP11.1@800,2275
  MidLayer1 w10: v1(555,1995) 705,1995 725,2015 725,2200 TP11.1@800,2275 ; v1(1765,1545) 1710,1600 1710,1720 1780,1790 1780,2160 1900,2280 v1(1900,2500)
  Bottom Layer w16: R16.2@555,1965 v1(555,1995) ; TP11.1@800,2275 970,2445 1455,2445 1510,2500 v1(1900,2500)
GPO2: R15.2 R19.1 TP12.1 U1.34 | length 3096.9
  Top Layer w8: U1.34@1668.11,1705.12 1735.12,1705.12 v1(1740,1710)
  Top Layer w16: TP12.1@800,2525 R19.1@800,2713.5 R19.1@800,2725
  MidLayer1 w10: v1(555,2070) 670,2070 700,2100 700,2305 800,2405 TP12.1@800,2525 ; v1(1740,1710) 1825,1795 1825,2050 1925,2150 v1(1925,2600)
  Bottom Layer w16: R15.2@555,2035 v1(555,2070) ; TP12.1@800,2525 850,2475 1250,2475 1375,2600 v1(1925,2600)
IN_BIAS: C7.1 R23.1 U1.36 | length 477.9
  Top Layer w8: U1.36@1668.11,1736.61 1701.61,1736.61 1720,1755
  Top Layer w16: 1720,1755 1885,1920 C7.1@1920,1920 ; v1(1885,1960) v1(1910,1960) v1(1935,1960) v1(1960,1960)
  Bottom Layer w16: v1(1885,1960) v1(1910,1960) v1(1935,1960) v1(1960,1960)
IN_BU: C17.1 R24.1 U1.27 | length 575.8
  Top Layer w8: U1.27@1668.11,1594.88 1755.12,1594.88
  Top Layer w16: 1755.12,1594.88 1800,1550 1800,1405 1825,1380 C17.1@1920,1380 ; v1(1875,1420) v1(1900,1420) v1(1925,1420) v1(1950,1420)
  Bottom Layer w16: v1(1875,1420) v1(1900,1420) v1(1925,1420) v1(1950,1420)
IN_CC: C19.1 R22.1 U1.25 | length 512.9
  Top Layer w8: U1.25@1668.11,1563.39 1691.61,1563.39 1735,1520
  Top Layer w16: 1735,1520 1775,1480 1775,1375 1860,1290 1920,1290 1905,1275 R22.1@1905,1210
IN_DC1: C6.2 R7.2 U1.1 | length 444.2
  Top Layer w8: 1385,1750 1398.39,1736.61 U1.1@1431.89,1736.61
  Top Layer w16: v1(1170,1910) v1(1195,1910) v1(1220,1910) v1(1245,1910)
  Top Layer w24: 1260,1875 1385,1750
  Top Layer w32: C6.2@1200,1875 1260,1875
  Bottom Layer w16: v1@1165,1910 v1(1170,1910) v1(1195,1910) v1(1220,1910) v1(1245,1910)
IN_DC2: C2.1 R3.1 U1.43 | length 374.2
  Top Layer w8: 1530.13,1836.13 1542.13,1824.13 U1.43@1542.13,1768.11
  Top Layer w16: v1(1430,1925) 1441.25,1925 v1(1455,1925) ; v1(1430,1945) 1440,1945 v1(1455,1945)
  Top Layer w32: C2.1@1440,2000 C2.1@1440,1991.54 1440,1945 1440,1926.25 1441.25,1925 1530.13,1836.13
  Bottom Layer w16: v1(1430,1925) v1(1455,1925) ; v1(1430,1945) v1(1455,1945)
IN_DC3: C5.1 R5.1 U1.37 | length 566.7
  Top Layer w16: v1(1880,2050) v1(1905,2050) v1(1930,2050) v1(1955,2050)
  Top Layer w32: 1649,1768 1674,1768 1810,1904 1810,1978 1847,2015 C5.1@1920,2015
  Bottom Layer w16: v1(1880,2050) v1(1905,2050) v1(1930,2050) v1(1955,2050)
IN_DC4: C18.2 R11.2 U1.12 | length 429.2
  Top Layer w8: 1385,1545 1403.39,1563.39 U1.12@1431.89,1563.39
  Top Layer w16: v1(1170,1460) v1(1195,1460) v1(1220,1460) v1(1245,1460) ; C18.2@1215,1425 1265,1425 1385,1545
  Bottom Layer w16: v1@1165,1460 v1(1170,1460) v1(1195,1460) v1(1220,1460) v1(1245,1460)
IN_LDO: C11.2 R8.2 U1.5 | length 366.6
  Top Layer w8: 1225,1685 1310,1685 1321,1674 1431.51,1674 U1.5@1431.89,1673.62
  Top Layer w16: v1(1170,1730) v1(1195,1730) v1(1220,1730) v1(1245,1730)
  Bottom Layer w16: v1@1165,1730 v1(1170,1730) v1(1195,1730) v1(1220,1730) v1(1245,1730)
IN_LS1: C14.1 JP3.2 R19.2 U1.31 | length 4897.6
  Top Layer w8: U1.31@1668.11,1657.87 1772.13,1657.87 1780,1650
  Top Layer w16: R19.2@800,2780 v1(800,2840) ; 1780,1650 1870,1560 C14.1@1920,1560 ; v1(1875,1600) v1(1900,1600) v1(1925,1600) v1(1950,1600)
  MidLayer1 w16: v1(800,2840) 2560,2840 2625,2775 2625,1250 2575,1200 JP3.2@2300,1200
  Bottom Layer w16: v1(1875,1600) v1(1900,1600) v1(1925,1600) v1(1950,1600)
  Bottom Layer w32: 1900,1575 2075,1575 2200,1450 2200,1250 2250,1200 JP3.2@2300,1200
IN_LS1_EXT: J1.3 JP3.1 | length 502.1
  Bottom Layer w16: J1.3@2800,1100 J1.3@2800,1100.59 J1.3@2800,1101
  Bottom Layer w32: JP3.1@2300,1100 2799,1100 J1.3@2799.5,1100.5 ; J1.3@2800,1100 J1.3@2799.5,1100.5 ; J1.3@2800,1101 J1.3@2799.5,1100.5
IN_LS2: C12.1 J2.2 U1.32 | length 1370.8
  Top Layer w8: U1.32@1668.11,1673.62 1791.38,1673.62 1800,1665
  Top Layer w16: 1800,1665 1815,1650 C12.1@1920,1650 ; v1(1875,1690) v1(1900,1690) v1(1925,1690) v1(1950,1690)
  Bottom Layer w16: v1(1875,1690) v1(1900,1690) v1(1925,1690) v1(1950,1690)
  Bottom Layer w32: 1910,1655 2095,1655 2262,1488 J2.2@2800,1488
IN_LS3: C13.2 J3.3 U1.6 | length 1852.7
  Top Layer w8: 1267.87,1657.87 U1.6@1431.89,1657.87
  Top Layer w16: v1(1180,1640) v1(1205,1640) v1(1230,1640) 1250,1640 v1(1255,1640)
  Top Layer w32: C13.2@1215,1605 1250,1640 v1@1257,1647
  Bottom Layer w16: v1@1175,1640 v1(1180,1640) v1(1205,1640) v1(1230,1640) v1(1255,1640)
  Bottom Layer w32: J3.3@300,974 904,974 975,1045 975,1565 1035,1625 1200,1625
IN_NCC: TP3.1 U1.18 | length 861.3
  Top Layer w8: v1@1503.28,1395 1542.13,1433.84 U1.18@1542.13,1531.89
  MidLayer1 w10: TP3.1@1425,775 1525,875 1525,960 1470,1015 1470,1385 1480,1395 v1(1500,1395)
INT_LDO: C9.1 TP6.1 U1.35 | length 950.8
  Top Layer w8: U1.35@1668.11,1720.87 1720.87,1720.87 1740,1740
  Top Layer w16: 1740,1740 1830,1830 1920,1830 v1@1920,1870 ; v1(1875,1870) v1(1900,1870) v1@1920,1870 ; v1(1950,1870) v1(1925,1870) v1@1920,1870
  Bottom Layer w16: v1(1875,1870) v1(1900,1870) v1(1925,1870) v1(1950,1870)
  Bottom Layer w32: 1915,1835 2110,1835 TP6.1@2300,2025
L1: L1.1 U1.48 | length 263
  Top Layer w32: L1.1@1320,1963.82 1320,1877 1429,1768 1451,1768
L2: L2.1 U1.42 | length 201.9
  Top Layer w8: U1.42@1557.87,1768.11 1557.87,1855.87 1570,1868
  Top Layer w32: 1570,1868 L2.1@1570,1965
